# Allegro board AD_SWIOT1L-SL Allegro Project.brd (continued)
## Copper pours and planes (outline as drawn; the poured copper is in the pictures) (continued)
(no net) on TOP: 25.57,57.04 25.57,57.84 24.09,57.84 23.71,58.22 23.71,59.06 23.27,59.49 21.29,59.49 21.14,59.34 21.14,58.22 21.27,58.09 21.93,58.09 22.98,57.04
(no net) on TOP: 98.52,63.15 94.94,63.15 94.53,63.56 94.53,64.88 98.49,64.88 98.77,64.6 98.77,63.41
(no net) on TOP: 86.53,74.23 86.53,65.41 89.14,65.41 89.14,67.01 89.78,67.65 89.78,74.23
(no net) on TOP: 31.59,55.41 31.59,55.02 34.27,55.02 35.31,53.98 35.97,53.98 36.33,53.62 36.33,52.73 36.46,52.6 39.45,52.6 39.45,55.41
(no net) on TOP: 96.87,55.86 96.87,54.59 97.32,54.14 98.26,54.14 98.64,53.76 98.64,48.01 98.01,47.38 98.01,45.6 90.85,45.6 90.85,47.56 91.33,48.04 94.15,48.04 94.5,48.4 94.5,52.87 93.51,53.86 92.55,53.86 92.55,54.14 92.42,54.26 92.42,55.86
(no net) on TOP: 90.08,67.22 89.7,66.84 89.7,62.87 90.87,61.71 90.87,59.7 91.15,59.42 91.48,59.42 91.86,59.04 91.86,58.12 91.94,58.05 93.56,58.05 93.77,57.84 93.77,56.17 97.63,56.17 97.88,56.42 97.88,59.34 96.38,60.84 96.38,62.62 94.63,62.62 93.97,63.28 93.97,66.84 93.59,67.22
(no net) on TOP: 25.57,55.41 25.57,55.01 22.88,55.01 21.85,53.99 21.17,53.99 20.84,53.66 20.84,52.72 20.71,52.59 17.66,52.59 17.66,55.06 18.01,55.41
(no net) on TOP: 31.59,54.81 31.59,54.02 33.08,54.02 33.46,53.63 33.46,52.8 33.89,52.36 35.87,52.36 36.02,52.52 36.02,53.63 35.9,53.76 35.24,53.76 34.19,54.81
(no net) on TOP: 25.57,54.81 25.57,54.02 24.09,54.02 23.71,53.63 23.71,52.8 23.27,52.36 21.29,52.36 21.14,52.52 21.14,53.63 21.27,53.76 21.93,53.76 22.98,54.81
(no net) on TOP: 31.59,56.45 31.59,56.84 34.29,56.84 35.31,57.86 36,57.86 36.33,58.19 36.33,59.13 36.46,59.26 39.45,59.26 39.45,56.74 39.16,56.45
CABLE+ on TOP: 91.58,88.22 91.58,96.43 89.88,98.13 89.88,105.15 87.57,105.15 87.57,101.84 86.93,101.2 83.3,101.2 83.3,98.46 85.23,98.46 88.28,95.41 88.28,89.44 89.86,87.87 91.23,87.87
CABLE- on TOP: 92.09,88.22 92.09,96.43 93.79,98.13 93.79,105.15 96.1,105.15 96.1,101.84 96.74,101.2 100.37,101.2 100.37,98.46 98.44,98.46 95.39,95.41 95.39,89.44 93.79,87.84 92.47,87.84
CH_1 on TOP (solid shape): 35.24,53.76 35.9,53.76 36.02,53.63 36.02,52.52 35.87,52.36 33.89,52.36 33.46,52.8 33.46,53.63 33.08,54.02 32.51,54.02 32.45,54.03 32.4,54.03 31.59,54.03 31.59,54.81 34.19,54.81
CH_1 on TOP: 34.54,19.97 34.54,16.59 36.22,16.59 38.84,13.97 40.23,13.97 41.07,13.13 41.07,9.22 40.39,8.53 40.39,5.31 40.61,5.08 43.28,5.08 43.54,5.33 43.54,13.11 41.73,14.91 41.73,19.72 41.48,19.97
CH_1 on BOTTOM: 34.89,53.86 36.03,53.86 45.46,44.43 45.46,23 39.59,17.13 34.61,17.13 34.38,17.35 34.38,18.51 34.65,18.78 39.35,18.78 44.24,23.66 44.24,43.45 35.26,52.43 34.89,52.43 34.76,52.56 34.76,53.73
CH_2 on TOP (solid shape): 36.02,59.34 36.02,58.22 35.9,58.09 35.24,58.09 34.19,57.04 31.59,57.04 31.59,57.82 32.4,57.82 32.45,57.82 32.51,57.84 33.08,57.84 33.46,58.22 33.46,59.06 33.89,59.49 35.87,59.49
CH_2 on TOP: 26.95,19.97 26.95,16.6 28.59,16.6 31.24,13.94 32.64,13.94 33.45,13.13 33.45,9.22 32.77,8.53 32.77,5.33 33.02,5.08 35.66,5.08 35.94,5.36 35.94,13.08 34.14,14.88 34.14,19.97
CH_2 on BOTTOM: 34.75,59.62 35.92,59.62 36.16,59.38 36.16,56.93 34.15,54.92 34.15,52.03 43.14,43.04 43.14,24.21 39.14,20.2 31.18,20.2 28.04,17.06 27.04,17.06 26.75,17.35 26.75,18.31 29.91,21.47 38.75,21.47 41.93,24.65 41.93,42.58 33.19,51.32 33.19,55.54 34.51,56.86 34.51,59.38
CH_3 on TOP (solid shape): 23.71,59.06 23.71,58.22 24.09,57.84 24.66,57.84 24.72,57.82 24.77,57.82 25.57,57.82 25.57,57.04 22.98,57.04 21.93,58.09 21.27,58.09 21.14,58.22 21.14,59.34 21.29,59.49 23.27,59.49
CH_3 on TOP: 19.33,19.97 19.33,16.6 21.02,16.6 23.62,14 25.02,14 25.81,13.21 25.81,9.22 25.12,8.53 25.12,5.33 25.37,5.08 28.07,5.08 28.32,5.33 28.32,13.13 26.52,14.94 26.52,19.97
CH_3 on BOTTOM: 21.28,59.62 22.39,59.62 22.65,59.37 22.65,57.27 24.3,55.62 24.3,51.47 14.82,42 14.82,21.37 17.44,18.75 20.72,18.75 20.89,18.58 20.89,17.35 20.72,17.18 17.1,17.18 13.6,20.68 13.6,42.41 23.28,52.09 23.28,55.2 21.02,57.46 21.02,59.37
CH_4 on TOP (solid shape): 25.57,54.03 24.77,54.03 24.72,54.03 24.66,54.02 24.09,54.02 23.71,53.63 23.71,52.8 23.27,52.36 21.29,52.36 21.14,52.52 21.14,53.63 21.27,53.76 21.93,53.76 22.98,54.81 25.57,54.81
CH_4 on TOP: 11.68,19.72 11.68,16.59 13.36,16.59 15.98,13.97 17.37,13.97 18.19,13.16 18.19,9.22 17.5,8.53 17.5,5.31 17.73,5.08 20.45,5.08 20.68,5.31 20.68,13.08 18.87,14.88 18.87,19.97 11.94,19.97
CH_4 on BOTTOM: 22.34,53.83 22.49,53.68 22.49,52.51 22.14,52.16 21.63,52.16 12.31,42.83 12.31,19.54 13.34,18.52 13.34,17.35 13.04,17.06 11.8,17.06 11.09,17.76 11.09,43.62 21.3,53.83
DATA_AND_POWER_N on TOP: 97.14,74.89 97.14,79.46 93.79,82.81 92.52,82.81 92.27,82.56 92.27,79.89 93.89,78.27 93.89,74.89
DATA_AND_POWER_P on TOP: 86.53,74.89 86.53,79.46 89.88,82.81 91.15,82.81 91.4,82.56 91.4,79.89 89.78,78.27 89.78,74.89
LTC9111_IN on TOP (solid shape): 97.61,56.28 95.06,56.28 95.06,59.03 97.61,59.03
LTC9111_IN on TOP (solid shape): 93.97,66.84 93.97,63.28 94.63,62.62 96.38,62.62 96.38,60.84 97.88,59.34 97.88,56.42 97.63,56.17 97.17,56.17 93.94,56.17 93.88,56.19 93.84,56.19 93.77,56.21 93.77,57.84 93.56,58.05 93.42,58.05 93.42,58.17 93.42,58.55 93.6,58.73 93.63,58.73 93.93,58.88 94.05,59.19 93.91,59.51 93.59,59.65 93.4,59.61 93.24,59.49 93.1,59.43 92.96,59.5 92.8,59.65 92.59,59.7 92.26,59.56 92.13,59.24 92.16,59.07 92.26,58.92 92.26,58.17 92.26,58.05 91.92,58.05 91.92,58.17 91.92,58.95 91.89,59.08 91.82,59.19 91.8,59.2 91.67,59.52 91.35,59.65 91.22,59.63 91.1,59.57 91.04,59.53 90.87,59.7 90.87,61.71 89.7,62.87 89.7,66.84 90.08,67.22 93.59,67.22
LX on TOP: 60.02,72.7 66.16,72.7 67.24,73.78 67.24,74.49 60.02,74.49
POWER_N on TOP (solid shape): 89.78,67.65 89.14,67.01 89.14,65.41 86.53,65.41 86.53,74.23 89.78,74.23
POWER_N on TOP: 84.04,54.95 84.04,56.35 84.17,56.47 85.54,56.47 85.66,56.35 85.66,54.95 85.54,54.82 84.17,54.82
POWER_N on L2_PWR: 82.84,73.64 91.68,73.64 91.68,64.3 92.9,63.08 92.9,58.2 91.25,58.2 90.59,58.86 90.59,59.52 90.24,59.88 88.05,59.88 86.4,58.23 86.4,52.84 85.69,52.13 82.84,52.13
POWER_P on TOP (solid shape): 97.14,65.41 94.53,65.41 94.53,67.01 93.89,67.65 93.89,74.23 97.14,74.23
POWER_P on TOP: 87.06,54.95 87.06,56.35 87.19,56.47 88.56,56.47 88.69,56.35 88.69,54.95 88.56,54.82 87.19,54.82
POWER_P on L2_PWR: 92.06,73.62 98.24,73.62 98.24,52.08 94.38,48.22 84.27,48.22 82.84,49.64 82.84,51.75 85.84,51.75 86.78,52.69 86.78,56.47 89.58,56.47 90.36,55.69 93.23,55.69 93.87,56.32 93.87,57.62 93.28,58.2 93.28,63.25 92.06,64.47
SPOE_OUT on TOP: 90.26,45.6 86.91,45.6 86.91,47.56 90.26,47.56
SPOE_OUT_O on TOP (solid shape): outline of 142 points within 90.85,45.6 98.64,55.86
SW on TOP: 70.98,16.7 69,16.7 66.59,14.28 64.76,14.28 64.76,19.29 66.11,19.29 66.11,18.27 70.98,18.27
SWP on TOP: 69.61,58.4 66.92,58.4 66.33,57.82 65.5,57.82 65.5,57.97 66.02,58.49 66.02,59.23 67.05,60.26 67.05,64.48 69.26,64.48 69.26,61.41 69.61,61.05
UNNAMED_6_CAP_I114_N1 on TOP (solid shape): 93.44,67.62 90.24,67.62 90.24,68.94 93.44,68.94
UNNAMED_6_CAP_I146_N1 on TOP (solid shape): 98.77,64.6 98.77,63.41 98.52,63.15 94.94,63.15 94.53,63.56 94.53,64.88 98.49,64.88
UNNAMED_6_CAPP_I143_N1 on TOP: 98.54,47.18 98.54,45.45 98.34,45.25 88.94,45.25 88.94,41.51 89.47,40.98 100.22,40.98 100.73,41.49 100.73,47.18 100.5,47.41 98.77,47.41
UNNAMED_7_ADLT8304_I142_EN on TOP: 61.81,9.38 61.13,9.38 60.7,9.81 58.66,9.81 58.11,10.37 58.11,11.18 58.82,11.9 61.2,11.9 61.81,11.29
UNNAMED_7_ADP1032_I2_SW2 on TOP: 61.38,52.51 61.38,50.33 62.22,49.49 62.22,46.14 60.9,46.14 60.9,51.39 61.08,51.57 61.08,52.51
UNNAMED_7_CAP_I154_N2 on TOP: 64.76,21.62 64.76,19.72 66.11,19.72 66.11,21.62
UNNAMED_7_CAP_I167_N1 on TOP: 88.23,17.36 88.23,16.59 88.49,16.34 91.09,16.34 91.34,16.59 91.34,17.36
UNNAMED_7_DIO_I14_P on TOP: 68.21,47.71 68.21,50.5 67.71,51.01 67.71,53.63 69.87,53.63 69.87,48.12 69.46,47.71
UNNAMED_7_DIOSCHOTTKY_I9_N on TOP: 69.66,64.48 69.66,62.73 73.83,62.73 73.83,64.48
UNNAMED_7_DIOSCHOTTKY_I132_P on TOP: 89.83,21.09 89.83,17.81 88.41,17.81 87.37,18.86 85.18,18.86 85.18,21.09
UNNAMED_7_DIOSCHOTTKY_I135_N on TOP: 66.51,18.58 66.51,21.62 68.09,21.62 68.09,18.58
UNNAMED_9_DIOBAV99LT1_I116_P on TOP: 33.67,25.67 33.67,27.25 38.83,27.25 39.08,26.99 39.08,26.26 37.76,26.26 37.18,25.67
UNNAMED_9_DIOBAV99LT1_I117_P on TOP: 33.67,42.64 33.67,44.21 38.83,44.21 39.08,43.96 39.08,43.22 37.76,43.22 37.18,42.64
UNNAMED_9_DIOBAV99LT1_I118_P on TOP: 23.56,43.26 23.56,41.69 18.4,41.69 18.15,41.94 18.15,42.68 19.47,42.68 20.06,43.26
UNNAMED_9_DIOBAV99LT1_I119_P on TOP: 23.56,26.3 23.56,24.72 18.4,24.72 18.15,24.98 18.15,25.71 19.47,25.71 20.06,26.3
VOUT1 on TOP: 62.27,50.81 62.27,51.27 61.89,51.65 61.89,52.51 61.58,52.51 61.58,50.53 62.52,49.59 62.52,42.17 71.77,42.17 71.77,46.82 63.9,46.82 63.26,47.46 63.26,49.82
VOUT2 on TOP: 60.08,52.51 60.08,50.91 58.61,49.44 58.61,47.96 58.36,47.71 56.99,47.71 56.73,47.46 56.73,44.26 57.57,43.42 60.19,43.42 60.19,49.69 60.52,50.02 60.52,51.39 60.39,51.52 60.39,52.51

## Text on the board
User.Comments: DETAIL A | 4.    RoHS COMPLIANCE: ASSEMBLY VENDOR SHOULD ASSURE COMPLIANCE | 5.    BOARDS TO BE SHIPPED SINGULATED AFTER ASSEMBLY PROCESS. | 6.    SMOOTHEN EDGES AND FREE FROM BURRS AFTER DEPANELIZATION. | DIRECTIVE 2002/95/EC). | WITH LEAD-FREE AND RoHS PCB ASSEMBLY STANDARDS (EU RoHS
Ref Des/Assembly Top: C | A | 1 | +
Ref Des/Silkscreen Top: GND | C | A | 1V8 | SLED 2 | FLED 2 | SLED 1 | FLED 1 | FLED 4 | SLED 4 | SLED 3 | FLED 3 | GND_ISO | VDDOK | CH_4 | CH_3 | P6 | CH_2 | CH_1 | P4 | 24V | 3V3_ISO | 3V3 | LED0 | LED1 | PWRGD | 24V_ISO | S2 | 24V FROM | MAX14906 | SUPPLY | POWER | INTERNAL | EXTERNAL | 36V | 1 | P3 | 1V1 | CABLE | AD-SWIOT1L-BRD | 08-073207 REV B Z | PRIMARY SIDE | +
PAGE_OUTLINE: K.JABATAN | V.ARMADO | M.VALE | 07JUL23 | 14APR23 | B | CHANGES AS PER ECR-114889 | M.SUCIU | CUSTOMER EVAL BOARD Z
DIMENSION: (THICKNESS AFTER PLATING) | FAB NOTES REVISION: 2ND NOVEMBER 2022 | 1.5 OZ, 0.0021" | 1 OZ, 0.0014" | 0.004 | 0.0454 | FINAL CU | CU CLAD | LAYER | NUMBER | THE FINISHED PCB THICKNESS TO BE: | 1 | 2 | 3 | 4 | TOP | L2_PWR | L3_GND | BOTTOM | NAME | COPPER THICKNESS | (OZ,INCH) | LAMINATION DIAGRAM | 0.062" +/-10% | DIELECTRIC | THICKNESS (INCH) | ISOLA 370HR/EQUIVALENT | MATERIALS | 8.   IMPEDANCE REQUIREMENTS: IF NO STACKUP IS DEFINED, THE VENDOR IS ALLOWED TO ADJUST THE DIELECTRIC | 13.  PLATING SPECIFICATION: | 1.   DIMENSIONS ARE IN INCHES (EXCEPT WHERE NOTED). | ALL DOCUMENTS & SPECIFICATIONS REFERRED TO BELOW SHOULD BE THE LATEST REVISIONS. | 2.  BOARD MATERIAL:(USE CHECKED ITEMS) | 3.   ALL LAMINATES & BONDING MATERIALS SHOULD BE SELECTED FROM IPC-4101 OR IPC-4103,(TG>170 DEGC TD>300 DEGC) | 4.   REFER TO IPC-6010 SERIES, CLASS 2 FOR FABRICATION. | 5.   REFER TO LAMINATION DIAGRAM FOR OVERALL BOARD THICKNESS, TOLERANCE APPLIES AFTER ALL LAMINATION AND PLATING | 6.   BOW & TWIST NOT TO EXCEED 0.0075 INCHES (0.75%) PER LINEAR INCH AND SHOULD BE MEASURED PER IPC-TM-650, METHOD 2.4.22. | 7.   ACCEPTABILITY PER ADI SPECIFICATION TST00115. | 9.   FILLET OPTIONS TO ENHANCE RELIABILITY AT PAD JUNCTIONS WHERE SPACING PERMITS. | 10.  THIEVING: | 11.  LAYER TO LAYER REGISTRATION SHALL BE WITHIN 0.003 INCHES. | 12.  DRILL SIZES ARE FINISHED HOLE SIZES. ALL HOLES SHALL BE LOCATED WITHIN 0.005 INCHES DTP,UNLESS SPECIFIED. | 14.  SURFACE FINISH: | 15.  SOLDERMASK: | 16.  APPLY SILKSCREEN TO BOTH SIDES USING A NON-CONDUCTIVE, EPOXY BASED INK PER ARTWORK. | (X) WHITE | ( ) OTHER | PROCESSES. FINISHED THICKNESS MEASURED FROM TOP COPPER TO BOTTOM COPPER. | (X)  ISOLA 370HR OR S1000-2 OR IT180 OR EQUIVALENT | ( )  ISOLA-FR408HR OR EQUIVALENT | ( )  ISOLA IS410 | ( )  MEGTRON 6 | ( )  NELCO-4000-13 | ( )  ROGERS 4350B | ( ) ROGERS 3003 | ( ) ARLON 85N | ( ) EM370D | ( )  OTHER ________________________ | ( ) FILLETS ALLOWED | (X) FILLETS NOT ALLOWED | ( ) VENDOR MAY ADD THIEVING TO COMPENSATE FOR LOW COPPER DENSITY AREAS MAINTAINING A MINIMUM | (X) VENDOR MAY NOT ADD THIEVING TO COMPENSATE FOR LOW COPPER DENSITY AREAS. | (X) LPI | ( ) OTHER_________ | COLOR | (X) GREEN | HINDER PROPER SOLDER WICKING. BARREL RELIEF ON SOLDERMASK ALLOWED IN UNFILLED VIA IN PAD HOLES. | (X) REFER TO LAMINATION DIAGRAM FOR FINISHED COPPER WEIGHT/THICKNESS REQUIRMENTS | (X) IMMERSION GOLD (ENIG) 1.58-3.94 MICRO INCHES OVER 118-236 MICRO INCHES MIN. OF ELECTROLESS NICKEL PER IPC-4552 | ( ) OSP (ORGANIC SOLDERABILITY PRESERVATIVE) | ( ) IMMERSION SILVER | ( ) SOFT WIRE BONDABLE GOLD 30-50 MICRO INCHES OF SOFT WIRE | ( ) EDGE CONNECTOR FINGERS ARE TO BE PLATED WITH 100 MICRO-INCHES(.0001") OF LOW STRESS | THICKNESS & TRACE WIDTHS TO MEET THE IMPEDANCE REQUIREMENT. IF SPECIFIED, THE VENDOR MUST | TRACE WIDTH & SPACING THAT IMPACT THE REQUIREMENTS MUST HAVE WRITTEN APPROVAL FROM ADI. | MINIMUM BARREL PLATING OF 0.001 INCHES. PLATED HOLES SHALL NOT BE ROUGH OR IRREGULAR SO AS TO | SOLDERMASK OVER BARE COPPER OR BARE GOLD (BOTH SIDES) TO MEET IPC-SM-840. | IF PRESENT,DO NOT MODIFY SOLDERMASK DEFINED PADS (MASK OPENINGS LESS THAN COPPER PAD) WITHOUT APPROVAL. | MEET THE REQUIREMENTS LISTED IN THE IMPEDANCE TABLE. ANY ADJUSTMENT MADE TO THE DEFINED STACKUP, | UL FLAMMABILITY RATING 94V-0. BOARD MATERIAL & CONSTRUCTION SHALL MEET THE REQUIREMENTS OF UL796/UL796F. | BONDABLE GOLD OVER 100-150 MICRO INCHES OF NICKEL | NICKEL UNDER 30 MICRO-INCHES (.0003') OF GOLD | 0.100 INCH CLEARANCE FROM ALL COPPER FEATURES, | THE STARTING COPPER WEIGHT/THICKNESS CAN VARY AS LONG AS THE FINISHED COPPER | WEIGHT/THICKNESS IS NOT LESS THAN THE SPECIFIED VALUE. | UNLESS OTHERWISE SPECIFIED | HOMOGENOUS MATERIALS IN THIS BOARD SHALL BE COMPLAINT WITH THE EU DIRECTIVE 2002/95/EC | WORKMANSHIP SHALL CONFORM TO IPC-A-600, CLASS 2. | REFERENCE | 21.  INTENTIONAL SHORTS: | 17.  FINAL ELECTRICAL TEST TO BE PERFORMED USING PROVIDED IPC-D-356A NETLIST OR ODB++ FORMAT FILE. | 22.  PEMNUTS: | 23.  MANUFACTURER TO ETCH/STAMP WITH PERMANENT NON-CONDUCTIVE INK | ON SECONDARY SIDE UNLESS OTHERWISE SPECIFIED: | 18.  A TIME DOMAIN REFLECTOMETER REPORT (TDR) FOR EACH IMPEDANCE CONTROLLED LAYER & A CERTIFICATE | 19.  IF PRESENT, ALL BLIND/BURIED VIAS WITH AN ASPECT RATIO <1:1 TO BE PLATED SHUT WITH COPPER WHEN | 20.  FOR VIA FILL INFORMATION REFER TO DRILL CHART: | 25. PANELIZATION: | 27.  MINIMUM DESIGN LINE WIDTH IS .006 INCH. | 28.  MINIMUM DESIGN LINE SPACING IS .006 INCH. | IS ACCEPTABLE, ALL OTHER INSTANCES MUST BE REPORTED. | IF AN INTENTIONAL SHORT REPORT IS SUPPLIED AND DOES NOT MATCH THE FAB DATA THEN | THE PCB SHALL HAVE A VERIFICATION STAMP. | (X)  NON-CONDUCTIVE EPOXY FILL ALL 0.010 INCHES DRILLED VIAS AND PLATED OVER | ( )  COPPER FILL ALL 0.XXXX INCHES DRILLED VIAS | ( ) PEMNUTS TO BE INSTALLED BY FABRICATOR | ( ) PEMNUTS NOT TO BE INSTALLED BY FABRICATOR | (X) NOT APPLICABLE | USED AS VIA-IN-PAD OR AS A STACKED VIA. BLIND/BURIED VIAS WITH AN ASPECT RATIO >1:1 TO BE FILLED | A. UL CODE-FLAMMABILITY RATING FOR THOSE APPROVED MATERIALS(IF APPLICABLE) | B. DATE CODE | C. LOT NUMBER | D. MANUFACTURER LOGO | BOARDS TO BE SHIPPED IN ARRAY AND KEPT INTACT | PANEL TO BE SUBJECTED TO CUSTOMERS APPROVAL | PANEL SOLDER PASTE STENCIL GERBER TO BE PROVIDED TO ANALOG | CAN'T BE PERFORMED BECAUSE THE TRACE LENGTH IS TOO SHORT ON THE OUTER LAYERS AT THE PIN ESCAPES | ADI APPROVAL IS REQUIRED. | OF COMPLIANCE SHALL BE PROVIDED BY VENDOR AT TIME OF SHIPMENT. INSTANCES WHERE TDR TESTING | WITH NON-CONDUCTIVE EPOXY. | "" | (REF) | DIA MAX | SEE NOTE 20 | NOTES: | TOOLING: | FINISH: | MATERIAL: | TESTING: | MISCELLANEOUS:
BODY_CENTER: LABEL PLACEMENT INFORMATION | HALF SIZE LABELS ARE | AVAILABLE IN THE LIBRARY | PLACE WHEELIE BIN LOGO | TO SUIT THE LAYOUT. | PLACE ROHS COMPLIANT LOGO | TO SUIT THE LAYOUT OR | DELETE IF NOT REQ'D. | PLACE CHINA ROHS COMPLIANT | LOGO TO SUIT THE LAYOUT OR | 1.THE BOARD SIZE CAN BE ADJUSTED TO SUIT THE APPLICATION. | 2.THE MOUNTING HOLES CAN BE MOVED/REMOVED TO SUIT THE APPLICATION. | 3.THE FIDUCIALS CAN BE MOVED TO SUIT THE APPLICATION. | 4.ADJUST THE DIMENSIONS TO SUIT THE APPLICATION. | 5.ADD THE CORRECT LAYER STACKUP ON FAB2 BASED ON THE NO OF LAYERS ON THE PCB. | 6.THE ROHS COMPLIANT AND WHEELIE BIN LOGO'S CAN BE MOVED TO THE DESIRED LOCATION. | HALF SIZE VERSIONS OF THE LABELS ARE AVAILABLE IN THE LIBRARY. | NOTES FOR TEMPLATE USAGE. | GENERIC D-SIZE TEMPLATE BR-067706A
User.11: A | C
User.17: L2_PWR | 08-      -06
User.18: L3_GND | 08-      -07
User.19: L3 GND | 08-      -09
User.45: FIGURE | SIZE | 10.0 | 30.0 | 45.0 | 55.0 | 65.0 | 70.0 | PLATED | DRILL CHART: TOP to BOTTOM | ALL UNITS ARE IN MILS | QTY | 1690 | 16 | 12 | 11 | 2 | 6 | TOLERANCE/NOTES
